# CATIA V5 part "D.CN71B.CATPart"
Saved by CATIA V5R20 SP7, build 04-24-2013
Part number: D.CN71B
Material "Nessuno"
Bounding box of the stored display mesh (mm): x 0 to 150.807, y -135.185 to 0, z -91.151 to 75.737
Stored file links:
  C:\Users\designer2\Desktop\Ottobre 2022\25-10-2022\04\Yori Evo 48V\D.CN71B.CATPart
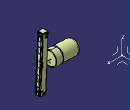
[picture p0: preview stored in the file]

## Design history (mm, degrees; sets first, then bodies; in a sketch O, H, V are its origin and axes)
AxisSystem1: origin (0, 0, 0), X (1, 0, 0), Y (0, 1, 0), Z (0, 0, 1)
Set1
  DatumSurface1
Body1 (main body), material "Nessuno"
